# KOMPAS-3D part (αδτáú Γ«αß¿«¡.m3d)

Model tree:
1. Эскиз:1
2. Операция выдавливания:1
     Расстояние 1 = 2
3. Эскиз:2
4. Вырезать элемент выдавливания:1
     Расстояние 1 = 10

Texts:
  stalker61
  Сплав АЛ8  ГОСТ 1583-93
